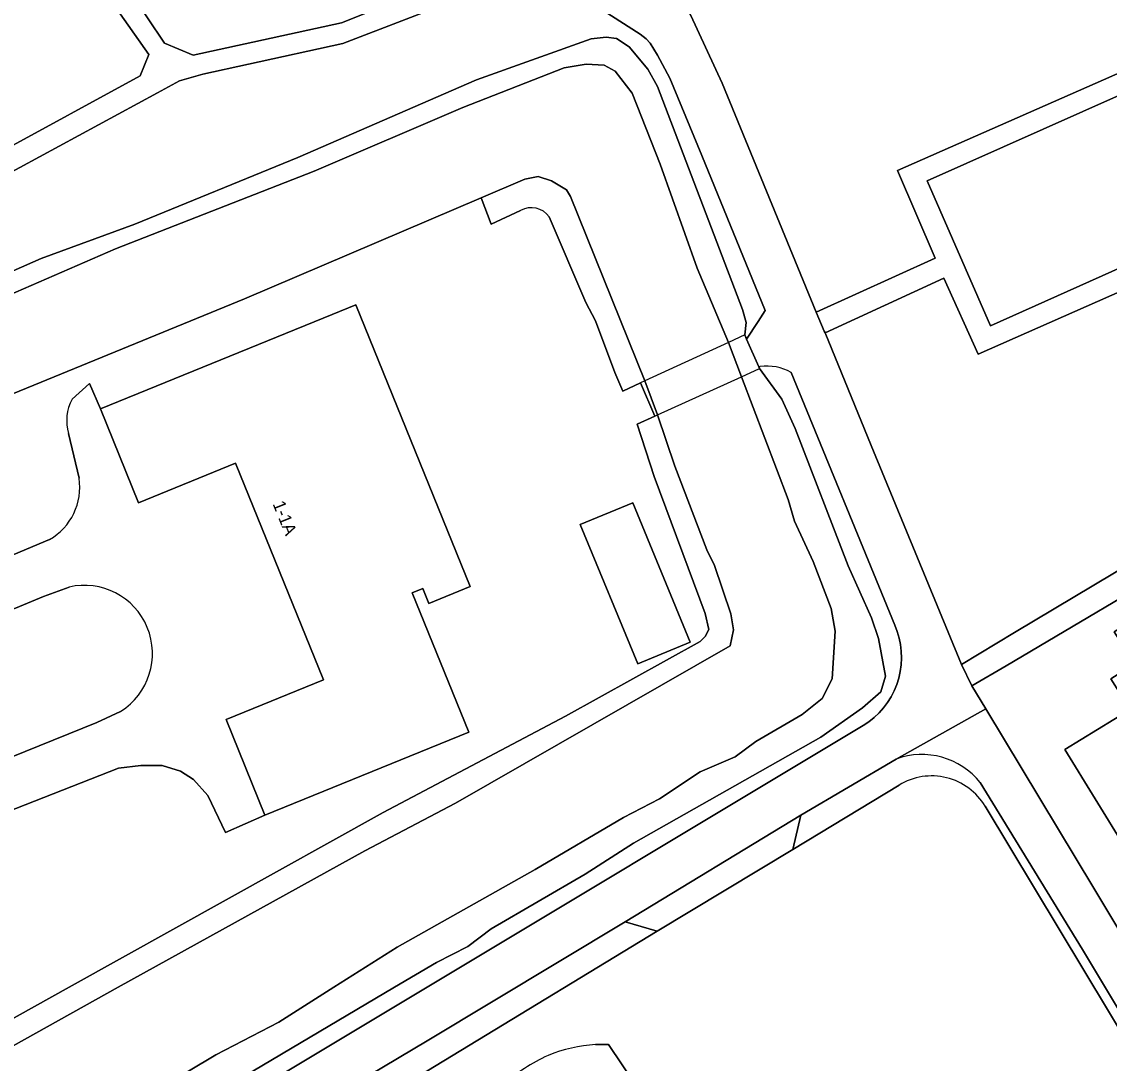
# Model space of a CAD drawing. Extents: x 162788 to 163838, y 385791 to 386523.
# Drawn here: x 163234.7 to 163321.5, y 386243.9 to 386327 of the extents above; entities that cross this region are included whole.
import ezdxf

# ---------------------------------------------------------------- set-up
doc = ezdxf.new("R2010")
doc.units = 0
for name, color, linetype in [('IMGEO_Dek', 7, 'Continuous'), ('IMGEO_Erf', 7, 'Continuous'), ('IMGEO_Gemengd_bos', 7, 'Continuous'), ('IMGEO_Groenvoorziening', 7, 'Continuous'), ('IMGEO_Oever', 7, 'Continuous'), ('IMGEO_Pand', 7, 'Continuous'), ('IMGEO_Pand_nummerreeks', 7, 'Continuous'), ('IMGEO_Parkeervlak_open', 7, 'Continuous'), ('IMGEO_Rijbaan_lokaal_open', 7, 'Continuous'), ('IMGEO_Voetpad_halfverhard', 7, 'Continuous'), ('IMGEO_Voetpad_open', 7, 'Continuous'), ('IMGEO_Waterloop', 7, 'Continuous'), ('IMGEO_Woonerf_open', 7, 'Continuous')]:
    doc.layers.add(name, color=color, linetype=linetype)

msp = doc.modelspace()

# ---------------------------------------------------------------- linework, layer by layer
at = {"layer": 'IMGEO_Dek'}
msp.add_lwpolyline([(163293.614, 386299.369), (163293.551, 386299.513), (163292.584, 386301.714), (163292.44, 386302.041), (163291.133, 386301.441), (163284.472, 386298.38), (163284.129, 386298.223), (163285.262, 386295.571), (163285.472, 386295.667), (163292.172, 386298.713)], close=True, dxfattribs=at)
at = {"layer": 'IMGEO_Erf'}
for points in [[(163353.891, 386241.041), (163361.83, 386247.495), (163364.388, 386250), (163367.592, 386253.137), (163370.682, 386255.929), (163375.708, 386260.443), (163377.288, 386261.582), (163388.388, 386271.954), (163388.788, 386272.873), (163388.748, 386273.873), (163388.129, 386275.573), (163369.598, 386309.184), (163358.272, 386329.726), (163357.191, 386329.246), (163367.738, 386310.106), (163368.442, 386308.828), (163368.586, 386308.579), (163331.921, 386286.666), (163328.501, 386284.648), (163313.313, 386275.651), (163310.566, 386274.054), (163311.675, 386272.212), (163320.288, 386257.903), (163335.62, 386232.403)], [(163274.545, 386311.969), (163272.188, 386310.889), (163271.388, 386312.975), (163252.5, 386304.929), (163230.211, 386295.802)], [(163202.054, 386229.702), (163238.524, 386250), (163263.566, 386263.938), (163278.138, 386271.642), (163288.891, 386277.589), (163289.291, 386277.988), (163289.571, 386278.548), (163289.29, 386279.827), (163285.213, 386290.763), (163283.842, 386294.937), (163285.262, 386295.571), (163284.129, 386298.223), (163282.711, 386297.567), (163282.076, 386299.042), (163280.519, 386303.163), (163279.76, 386304.643), (163276.832, 386311.461)], [(163238.746, 386296.921), (163240.141, 386298.174), (163241.008, 386296.157), (163259.496, 386303.663), (163261.4, 386304.436), (163270.523, 386281.968), (163267.233, 386280.632), (163266.757, 386281.806), (163265.903, 386281.459), (163270.416, 386270.343), (163254.139, 386263.734), (163250.985, 386262.347), (163249.593, 386265.308), (163248.435, 386266.589), (163247.396, 386267.249), (163245.936, 386267.691), (163244.237, 386267.692), (163242.459, 386267.474), (163219.469, 386258.476)], [(163239.308, 386290.618), (163238.468, 386294.193)], [(163213.904, 386276.053), (163236.95, 386285.724)]]:
    msp.add_lwpolyline(points, dxfattribs=at)
for points in [[(163279.311, 386286.911), (163283.505, 386288.642), (163288.093, 386277.524), (163283.897, 386275.799)], [(163331.468, 386266.404), (163322.825, 386261.107), (163317.999, 386268.982), (163323.193, 386272.15), (163321.652, 386274.6), (163323.552, 386275.796), (163321.936, 386278.366), (163324.464, 386279.955), (163325.896, 386277.677), (163326.626, 386278.135), (163328.395, 386275.322), (163329.109, 386275.758), (163330.796, 386273.076), (163328.286, 386271.513), (163329.901, 386268.92)]]:
    msp.add_lwpolyline(points, close=True, dxfattribs=at)
for centre, radius, start, end in [((163275.406, 386310.441), 1.753, 35.55549, 119.3975), ((163241.944, 386295.217), 3.624, 151.95197, 196.41062), ((163234.542, 386289.899), 4.82, 299.97643, 8.57269)]:
    msp.add_arc(centre, radius, start, end, dxfattribs=at)
at = {"layer": 'IMGEO_Gemengd_bos'}
for points in [[(163223.197, 386360.203), (163204.76, 386350.872), (163146.678, 386322.304), (163163.05, 386304.455), (163174.705, 386298.212), (163176.619, 386297.321), (163178.558, 386296.506), (163181.405, 386295.624), (163182.613, 386295.399), (163184.727, 386295.242), (163187.035, 386295.455), (163188.867, 386295.915), (163216.323, 386307.387), (163221.539, 386310.385), (163244.172, 386322.726), (163244.865, 386324.422), (163239.284, 386332.366), (163230.094, 386349.777), (163225.521, 386357.53)], [(163269.903, 386343.782), (163266.438, 386352.065), (163243.382, 386343.099), (163239.727, 386342.7), (163235.217, 386343.897), (163240.704, 386333.427), (163246.128, 386325.327), (163248.412, 386324.358), (163260.256, 386326.939), (163274.506, 386332.646)]]:
    msp.add_lwpolyline(points, close=True, dxfattribs=at)
for points in [[(163275.875, 386331.291), (163260.37, 386325.285), (163252.83, 386323.637), (163249.196, 386322.854), (163247.317, 386322.31), (163245.563, 386321.359), (163220.431, 386307.743)], [(163231.773, 386306.186), (163236.271, 386308.142), (163243.767, 386310.895), (163256.761, 386316.202), (163271.034, 386322.389), (163280.171, 386325.681), (163281.39, 386325.8), (163282.189, 386325.7), (163283.208, 386325.038), (163284.706, 386323.257), (163285.485, 386321.876), (163292.269, 386304.069), (163292.549, 386303.029), (163292.44, 386302.041), (163292.584, 386301.714), (163293.505, 386303.108), (163294.055, 386303.982), (163289.008, 386316.367), (163286.454, 386322.532), (163285.485, 386324.372), (163284.902, 386325.32), (163284.575, 386325.68), (163284.095, 386326.048), (163279.133, 386329.235)], [(163304.751, 386266.136), (163296.268, 386260.982), (163285.446, 386254.483), (163254.095, 386235.436), (163254.589, 386235.004), (163262.704, 386227.157), (163272.381, 386216.793), (163275.53, 386213.523), (163282.746, 386217.012), (163283.132, 386217.512), (163279.555, 386222.751), (163274.345, 386231.029), (163270, 386237.609), (163270.26, 386238.068)], [(163280.535, 386245.437), (163281.575, 386245.437), (163287.173, 386237.078), (163293.429, 386226.72), (163294.292, 386224.795), (163295.345, 386224.545), (163299.832, 386224.953), (163303.289, 386225.225), (163304.457, 386225.417), (163306.785, 386226.045), (163314.356, 386228.407), (163317.791, 386229.476), (163319.029, 386229.803), (163320.384, 386230.073), (163323.553, 386230.6), (163331.222, 386231.885), (163311.632, 386264.441)]]:
    msp.add_lwpolyline(points, dxfattribs=at)
for centre, radius, start, end in [((163307.348, 386261.863), 5, 31.03438, 121.28923), ((163281.374, 386233.134), 12.332, 93.90068, 112.08195), ((163283.456, 386230.066), 15.976, 114.86835, 130.22636)]:
    msp.add_arc(centre, radius, start, end, dxfattribs=at)
at = {"layer": 'IMGEO_Groenvoorziening'}
for points in [[(163324.634, 386323.978), (163327.475, 386326.656), (163331.906, 386327.82), (163325.377, 386341.987), (163287.919, 386327.789), (163288.126, 386327.517), (163290.624, 386322.14), (163298.143, 386303.852), (163307.627, 386308.181), (163304.632, 386315.163)], [(163330.768, 386325.903), (163328.194, 386325.116), (163325.513, 386322.577), (163306.991, 386314.342), (163312.064, 386302.781), (163330.648, 386311.098), (163334.468, 386311.377), (163338.148, 386314.375), (163338.135, 386320.556), (163337.359, 386321.985), (163332.672, 386326.272)], [(163338.814, 386312.688), (163334.967, 386309.618), (163331.268, 386309.419), (163311.063, 386300.521), (163308.325, 386306.581), (163298.844, 386302.201), (163302.536, 386293.221), (163309.731, 386275.744), (163313.964, 386278.304), (163345.761, 386297.279)], [(163285.446, 386254.483), (163282.904, 386255.221), (163267.081, 386245.733), (163252.174, 386236.838), (163253.656, 386235.82), (163254.095, 386235.436)]]:
    msp.add_lwpolyline(points, close=True, dxfattribs=at)
for points in [[(163293.668, 386299.53), (163293.551, 386299.513), (163293.614, 386299.369), (163295.404, 386296.908), (163296.464, 386294.569), (163300.704, 386283.616), (163302.564, 386279.479), (163303.105, 386277.82), (163303.685, 386274.822), (163303.305, 386273.583), (163301.826, 386272.305), (163298.507, 386269.949), (163283.555, 386261.504), (163279.697, 386259.029), (163272.2, 386254.657), (163270.341, 386253.259), (163267.843, 386251.982), (163264.496, 386250), (163252.47, 386242.879)], [(163227.747, 386226.411), (163301.902, 386270.889), (163302.35, 386271.188), (163302.771, 386271.523), (163303.162, 386271.893), (163303.52, 386272.294), (163303.843, 386272.725), (163304.128, 386273.181), (163304.374, 386273.66), (163304.578, 386274.158), (163304.738, 386274.672), (163304.855, 386275.197), (163304.927, 386275.731), (163304.953, 386276.268), (163304.933, 386276.806), (163304.868, 386277.34), (163304.758, 386277.867), (163304.604, 386278.382), (163304.406, 386278.883), (163296.142, 386299.055)], [(163238.509, 386281.931), (163236.464, 386281.191), (163223.911, 386275.964), (163211.608, 386270.287)], [(163240.72, 386271.133), (163242.625, 386272.014)], [(163215.153, 386261.037), (163220.05, 386262.773), (163240.72, 386271.133)], [(163304.521, 386268.211), (163296.911, 386263.731), (163296.268, 386260.982), (163304.751, 386266.136)], [(163311.632, 386264.441), (163331.222, 386231.885), (163332.017, 386232.018), (163331.635, 386232.654), (163323.947, 386245.43), (163319.391, 386253.017), (163311.237, 386266.337)]]:
    msp.add_lwpolyline(points, dxfattribs=at)
for centre, radius, start, end in [((163294.185, 386295.542), 4.021, 60.87746, 97.38585), ((163239.725, 386276.623), 5.445, 302.17808, 102.90321), ((163306.567, 386262.571), 6, 38.88259, 109.93547), ((163307.348, 386261.863), 5, 31.03438, 121.28923)]:
    msp.add_arc(centre, radius, start, end, dxfattribs=at)
at = {"layer": 'IMGEO_Oever'}
for points in [[(163252.47, 386242.879), (163264.496, 386250), (163267.843, 386251.982), (163270.341, 386253.259), (163272.2, 386254.657), (163279.697, 386259.029), (163283.555, 386261.504), (163298.507, 386269.949), (163301.826, 386272.305), (163303.305, 386273.583), (163303.685, 386274.822), (163303.105, 386277.82), (163302.564, 386279.479), (163300.704, 386283.616), (163296.464, 386294.569), (163295.404, 386296.908), (163293.614, 386299.369), (163293.551, 386299.513), (163292.584, 386301.714), (163292.44, 386302.041), (163292.549, 386303.029), (163292.269, 386304.069), (163285.485, 386321.876), (163284.706, 386323.257), (163283.208, 386325.038), (163282.189, 386325.7), (163281.39, 386325.8), (163280.171, 386325.681), (163271.034, 386322.389), (163256.761, 386316.202), (163243.767, 386310.895), (163236.271, 386308.142), (163231.773, 386306.186)], [(163229.954, 386303.609), (163242.228, 386308.924), (163258.08, 386315.121), (163269.934, 386320.19), (163278.034, 386323.346), (163279.789, 386323.642), (163281.229, 386323.56), (163282.108, 386323.1), (163283.466, 386321.338), (163285.681, 386315.676), (163288.634, 386307.373), (163291.133, 386301.441), (163292.172, 386298.713), (163295.905, 386288.914), (163296.406, 386287.195), (163297.905, 386283.958), (163299.326, 386280.22), (163299.646, 386278.421), (163299.406, 386274.605), (163298.627, 386273.046), (163297.008, 386271.768), (163293.33, 386269.612), (163291.67, 386268.374), (163288.892, 386267.177), (163285.633, 386265.04), (163282.755, 386263.543), (163275.718, 386259.391), (163264.704, 386253.203), (163259.647, 386250), (163255.249, 386247.214), (163250.233, 386244.613), (163237.257, 386236.873)], [(163201.415, 386227.105), (163242.438, 386250), (163262.127, 386260.881), (163269.342, 386264.693), (163291.27, 386277.247), (163291.53, 386278.527), (163291.329, 386279.805), (163290.03, 386283.663), (163289.41, 386284.903), (163286.871, 386291.58), (163285.472, 386295.667), (163284.472, 386298.38), (163278.524, 386313.101), (163278.214, 386313.615), (163277.027, 386314.344), (163275.952, 386314.698), (163274.888, 386314.466), (163271.388, 386312.975), (163272.188, 386310.889), (163274.545, 386311.969)], [(163276.832, 386311.461), (163279.76, 386304.643), (163280.519, 386303.163), (163282.076, 386299.042), (163282.711, 386297.567), (163284.129, 386298.223), (163285.262, 386295.571), (163283.842, 386294.937), (163285.213, 386290.763), (163289.29, 386279.827), (163289.571, 386278.548), (163289.291, 386277.988), (163288.891, 386277.589), (163278.138, 386271.642), (163263.566, 386263.938), (163238.524, 386250), (163202.054, 386229.702), (163201.455, 386229.643), (163200.895, 386229.904), (163200.495, 386230.524), (163192.642, 386244.303)], [(163280.15, 386242.563), (163292.504, 386223.397), (163294.292, 386224.795), (163293.429, 386226.72), (163287.173, 386237.078), (163281.575, 386245.437)], [(163281.575, 386245.437), (163280.535, 386245.437)]]:
    msp.add_lwpolyline(points, dxfattribs=at)
for centre, radius, start, end in [((163275.406, 386310.441), 1.753, 35.55549, 119.3975), ((163281.374, 386233.134), 12.332, 93.90068, 112.08195), ((163283.456, 386230.066), 15.976, 114.86835, 130.22636)]:
    msp.add_arc(centre, radius, start, end, dxfattribs=at)
at = {"layer": 'IMGEO_Pand'}
for points in [[(163261.4, 386304.436), (163259.496, 386303.663), (163241.008, 386296.157), (163244.052, 386288.66), (163251.806, 386291.808), (163258.82, 386274.532), (163251.038, 386271.372), (163254.139, 386263.734), (163270.416, 386270.343), (163265.903, 386281.459), (163266.757, 386281.806), (163267.233, 386280.632), (163270.523, 386281.968)], [(163283.505, 386288.642), (163279.311, 386286.911), (163283.897, 386275.799), (163288.093, 386277.524)], [(163329.901, 386268.92), (163328.286, 386271.513), (163330.796, 386273.076), (163329.109, 386275.758), (163328.395, 386275.322), (163326.626, 386278.135), (163325.896, 386277.677), (163324.464, 386279.955), (163321.936, 386278.366), (163323.552, 386275.796), (163321.652, 386274.6), (163323.193, 386272.15), (163317.999, 386268.982), (163322.825, 386261.107), (163331.468, 386266.404)]]:
    msp.add_lwpolyline(points, close=True, dxfattribs=at)
at = {"layer": 'IMGEO_Parkeervlak_open'}
msp.add_lwpolyline([(163296.911, 386263.731), (163282.904, 386255.221), (163285.446, 386254.483), (163296.268, 386260.982)], close=True, dxfattribs=at)
at = {"layer": 'IMGEO_Rijbaan_lokaal_open'}
for points in [[(163320.288, 386257.903), (163311.675, 386272.212), (163304.521, 386268.211)], [(163311.237, 386266.337), (163319.391, 386253.017), (163323.947, 386245.43), (163331.635, 386232.654)], [(163335.62, 386232.403), (163320.288, 386257.903)]]:
    msp.add_lwpolyline(points, dxfattribs=at)
msp.add_arc((163306.567, 386262.571), 6, 38.88259, 109.93547, dxfattribs=at)
at = {"layer": 'IMGEO_Voetpad_halfverhard'}
for points in [[(163220.431, 386307.743), (163245.563, 386321.359), (163247.317, 386322.31), (163249.196, 386322.854), (163252.83, 386323.637), (163260.37, 386325.285), (163275.875, 386331.291), (163275.089, 386331.787), (163274.506, 386332.646), (163260.256, 386326.939), (163248.412, 386324.358), (163246.128, 386325.327), (163240.704, 386333.427), (163235.217, 386343.897), (163239.727, 386342.7), (163243.382, 386343.099), (163266.438, 386352.065), (163265.569, 386354.141), (163246.297, 386346.078), (163240.873, 386344.481), (163236.534, 386344.994), (163233.336, 386347.39)], [(163230.094, 386349.777), (163239.284, 386332.366), (163244.865, 386324.422), (163244.172, 386322.726), (163221.539, 386310.385)], [(163324.634, 386323.978), (163304.632, 386315.163), (163307.627, 386308.181), (163298.143, 386303.852), (163298.786, 386302.343), (163298.844, 386302.201), (163308.325, 386306.581), (163311.063, 386300.521), (163331.268, 386309.419)], [(163345.761, 386297.279), (163313.964, 386278.304), (163309.731, 386275.744), (163310.566, 386274.054), (163313.313, 386275.651), (163328.501, 386284.648)]]:
    msp.add_lwpolyline(points, dxfattribs=at)
msp.add_lwpolyline([(163330.768, 386325.903), (163332.672, 386326.272), (163337.359, 386321.985), (163338.135, 386320.556), (163338.148, 386314.375), (163334.468, 386311.377), (163330.648, 386311.098), (163312.064, 386302.781), (163306.991, 386314.342), (163325.513, 386322.577), (163328.194, 386325.116)], close=True, dxfattribs=at)
at = {"layer": 'IMGEO_Voetpad_open'}
msp.add_lwpolyline([(163293.614, 386299.369), (163293.551, 386299.513), (163292.584, 386301.714), (163292.44, 386302.041), (163291.133, 386301.441), (163284.472, 386298.38), (163284.129, 386298.223), (163285.262, 386295.571), (163285.472, 386295.667), (163292.172, 386298.713)], close=True, dxfattribs=at)
for points in [[(163242.459, 386267.474), (163244.237, 386267.692), (163245.936, 386267.691), (163247.396, 386267.249), (163248.435, 386266.589), (163249.593, 386265.308), (163250.985, 386262.347), (163254.139, 386263.734), (163251.038, 386271.372), (163258.82, 386274.532), (163251.806, 386291.808), (163244.052, 386288.66), (163241.008, 386296.157), (163240.141, 386298.174), (163238.746, 386296.921)], [(163238.468, 386294.193), (163239.308, 386290.618)], [(163236.95, 386285.724), (163213.904, 386276.053), (163209.26, 386273.269), (163205.343, 386270.508), (163202.246, 386267.461), (163193.968, 386258.51), (163190.268, 386255.096), (163188.065, 386253.921), (163187.663, 386253.556), (163189.98, 386249.349), (163191.696, 386250), (163196.641, 386251.876), (163201.518, 386253.451), (163207.396, 386255.086), (163212.113, 386256.103), (163219.469, 386258.476), (163242.459, 386267.474)], [(163211.608, 386270.287), (163223.911, 386275.964), (163236.464, 386281.191), (163238.509, 386281.931)], [(163242.625, 386272.014), (163240.72, 386271.133), (163220.05, 386262.773), (163215.153, 386261.037)]]:
    msp.add_lwpolyline(points, dxfattribs=at)
for centre, radius, start, end in [((163241.944, 386295.217), 3.624, 151.95197, 196.41062), ((163234.542, 386289.899), 4.82, 299.97643, 8.57269), ((163239.725, 386276.623), 5.445, 302.17808, 102.90321)]:
    msp.add_arc(centre, radius, start, end, dxfattribs=at)
at = {"layer": 'IMGEO_Waterloop'}
for points in [[(163237.257, 386236.873), (163250.233, 386244.613), (163255.249, 386247.214), (163259.647, 386250), (163264.704, 386253.203), (163275.718, 386259.391), (163282.755, 386263.543), (163285.633, 386265.04), (163288.892, 386267.177), (163291.67, 386268.374), (163293.33, 386269.612), (163297.008, 386271.768), (163298.627, 386273.046), (163299.406, 386274.605), (163299.646, 386278.421), (163299.326, 386280.22), (163297.905, 386283.958), (163296.406, 386287.195), (163295.905, 386288.914), (163292.172, 386298.713), (163291.133, 386301.441), (163288.634, 386307.373), (163285.681, 386315.676), (163283.466, 386321.338), (163282.108, 386323.1), (163281.229, 386323.56), (163279.789, 386323.642), (163278.034, 386323.346), (163269.934, 386320.19), (163258.08, 386315.121), (163242.228, 386308.924), (163229.954, 386303.609)], [(163230.211, 386295.802), (163252.5, 386304.929), (163271.388, 386312.975), (163274.888, 386314.466), (163275.952, 386314.698), (163277.027, 386314.344), (163278.214, 386313.615), (163278.524, 386313.101), (163284.472, 386298.38), (163285.472, 386295.667), (163286.871, 386291.58), (163289.41, 386284.903), (163290.03, 386283.663), (163291.329, 386279.805), (163291.53, 386278.527), (163291.27, 386277.247), (163269.342, 386264.693)], [(163269.342, 386264.693), (163262.127, 386260.881), (163242.438, 386250), (163201.415, 386227.105), (163200.875, 386226.925), (163199.696, 386227.185), (163199.276, 386227.566), (163195.418, 386234.625), (163190.782, 386242.484), (163187.14, 386249.053), (163185.759, 386251.758), (163175.833, 386269.654)]]:
    msp.add_lwpolyline(points, dxfattribs=at)
at = {"layer": 'IMGEO_Woonerf_open'}
for points in [[(163257.813, 386372.455), (163258.983, 386369.883), (163265.569, 386354.141), (163266.438, 386352.065), (163269.903, 386343.782), (163274.506, 386332.646), (163275.089, 386331.787), (163275.875, 386331.291), (163279.133, 386329.235), (163284.095, 386326.048), (163284.575, 386325.68), (163284.902, 386325.32), (163285.485, 386324.372), (163286.454, 386322.532), (163289.008, 386316.367), (163294.055, 386303.982), (163293.505, 386303.108), (163292.584, 386301.714), (163293.551, 386299.513), (163293.668, 386299.53)], [(163252.174, 386236.838), (163267.081, 386245.733), (163282.904, 386255.221), (163296.911, 386263.731), (163304.521, 386268.211), (163311.675, 386272.212), (163310.566, 386274.054), (163309.731, 386275.744), (163302.536, 386293.221), (163298.844, 386302.201), (163298.786, 386302.343), (163298.143, 386303.852), (163290.624, 386322.14), (163288.126, 386327.517)], [(163296.142, 386299.055), (163304.406, 386278.883), (163304.604, 386278.382), (163304.758, 386277.867), (163304.868, 386277.34), (163304.933, 386276.806), (163304.953, 386276.268), (163304.927, 386275.731), (163304.855, 386275.197), (163304.738, 386274.672), (163304.578, 386274.158), (163304.374, 386273.66), (163304.128, 386273.181), (163303.843, 386272.725), (163303.52, 386272.294), (163303.162, 386271.893), (163302.771, 386271.523), (163302.35, 386271.188), (163301.902, 386270.889), (163227.747, 386226.411)]]:
    msp.add_lwpolyline(points, dxfattribs=at)
msp.add_arc((163294.185, 386295.542), 4.021, 60.87746, 97.38585, dxfattribs=at)

# ---------------------------------------------------------------- texts
at = {"layer": 'IMGEO_Pand_nummerreeks'}
msp.add_text('1-1A', height=1, rotation=292.09877, dxfattribs=at).set_placement((163254.739, 386288.573))

doc.saveas('drawing.dxf')
